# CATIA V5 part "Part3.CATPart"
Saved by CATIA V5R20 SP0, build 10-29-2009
Part number: Part3
Bounding box of the stored display mesh (mm): x 123.011 to 129.361, y 56.551 to 62.59, z -33.401 to 33.401
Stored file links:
  C:\Users\TAK SYS\Desktop\Part3.CATPart
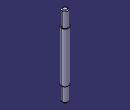
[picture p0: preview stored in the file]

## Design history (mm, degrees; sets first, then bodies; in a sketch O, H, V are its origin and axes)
Body1 (main body)
  Sketch1 on xy-plane, origin (0, 0, 0), H (1, 0, 0), V (0, 1, 0)
    circle A1 centre (126.1858, 59.5707) radius 2.413
    circle A2 centre (126.1858, 59.5707) radius 3.175
    radius A1 = 2.413
    radius A2 = 3.175
  Pad1: profile Sketch1.A1, length 20.701, mirrored extent
  Pad2: profile Sketch1.A1, length 33.401, mirrored extent
  Chamfer1: length 0.762, angle 45, on edge [face of Pad2 from Sketch1.A1 | end face of Pad2]
  Chamfer2: length 0.762, angle 45, on edge [start face of Pad2 | face of Pad2 from Sketch1.A1]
